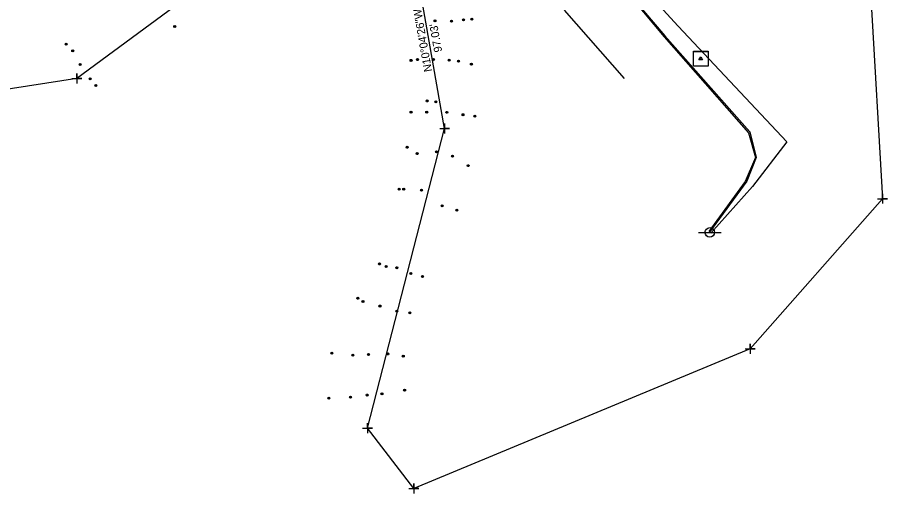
# Model space of a CAD drawing. Extents: x 1550153 to 1552579, y 809637 to 812160.
# Drawn here: x 1552025.7 to 1552462.6, y 809636.9 to 809876 of the extents above; entities that cross this region are included whole.
import ezdxf

# ---------------------------------------------------------------- set-up
doc = ezdxf.new("R2010")
doc.units = 0
for name, color, linetype in [('CTL Secondary Horizontal and Vertical CELL', 7, 'Continuous'), ('Default', 7, 'Continuous'), ('Exist Property Corner CELL', 7, 'Continuous'), ('Exist Property Line', 7, 'Continuous'), ('Exist Property Line Text', 7, 'Continuous'), ('Exist Right of Way Line', 7, 'Continuous'), ('Exist Survey Control Group', 7, 'Continuous'), ('Exist Utilities Telephone Pole CELL', 7, 'Continuous'), ('Exist Utilities Telephone UG Cable SUE LOS B', 7, 'Continuous'), ('Exist Utilities Telephone UG FO SUE LOS B', 7, 'Continuous')]:
    doc.layers.add(name, color=color, linetype=linetype)

# ---------------------------------------------------------------- blocks, each defined once
blk = doc.blocks.new('SurveyPointCell')
at = {"layer": 'Default'}
for p, q in [((-0.5, 0), (0.5, 0)), ((0, -0.5), (0, 0.5))]:
    blk.add_line(p, q, dxfattribs=at)
blk.add_circle((0, 0), 0.5, dxfattribs=at)

msp = doc.modelspace()

# ---------------------------------------------------------------- linework, layer by layer
at = {"layer": 'CTL Secondary Horizontal and Vertical CELL'}
for p, q in [((1552368.8, 809855.26), (1552368.8, 809855.26)), ((1552368.8, 809855.25), (1552368.8, 809855.25))]:
    msp.add_line(p, q, dxfattribs=at)
for points in [[(1552365.12, 809858.96), (1552372.53, 809858.96), (1552372.53, 809851.54), (1552365.12, 809851.54)], [(1552365.12, 809858.95), (1552372.53, 809858.95), (1552372.53, 809851.52), (1552365.12, 809851.52)]]:
    msp.add_lwpolyline(points, close=True, dxfattribs=at)
at = {"layer": 'Default'}
msp.add_line((1552368.8, 809855.26), (1552368.8, 809855.26), dxfattribs=at)
at = {"layer": 'Exist Property Corner CELL'}
for p, q in [((1552055.49, 809845.39), (1552055.49, 809845.39)), ((1552240.21, 809820.15), (1552240.21, 809820.15)), ((1552460.14, 809784.97), (1552460.14, 809784.97)), ((1552393.67, 809709.51), (1552393.67, 809709.51)), ((1552201.43, 809669.72), (1552201.43, 809669.72)), ((1552224.68, 809639.39), (1552224.68, 809639.39))]:
    msp.add_line(p, q, dxfattribs=at)
for points in [[(1552052.99, 809845.39), (1552057.99, 809845.39), (1552055.49, 809845.39), (1552055.49, 809847.89), (1552055.49, 809842.89)], [(1552237.71, 809820.15), (1552242.71, 809820.15), (1552240.21, 809820.15), (1552240.21, 809822.65), (1552240.21, 809817.65)], [(1552457.64, 809784.97), (1552462.64, 809784.97), (1552460.14, 809784.97), (1552460.14, 809787.47), (1552460.14, 809782.47)], [(1552391.17, 809709.51), (1552396.17, 809709.51), (1552393.67, 809709.51), (1552393.67, 809712.01), (1552393.67, 809707.01)], [(1552198.93, 809669.72), (1552203.93, 809669.72), (1552201.43, 809669.72), (1552201.43, 809672.22), (1552201.43, 809667.22)], [(1552222.18, 809639.39), (1552227.18, 809639.39), (1552224.68, 809639.39), (1552224.68, 809641.89), (1552224.68, 809636.89)]]:
    msp.add_lwpolyline(points, dxfattribs=at)
at = {"layer": 'Exist Property Line'}
for p, q in [((1552439.52, 810134.36), (1552460.15, 809784.96)), ((1552179.62, 809936.85), (1552055.49, 809845.39)), ((1552240.21, 809820.15), (1552223.24, 809915.69)), ((1552055.49, 809845.39), (1551998.3, 809836.53)), ((1552201.43, 809669.72), (1552240.21, 809820.15)), ((1552460.14, 809784.97), (1552393.67, 809709.51)), ((1552393.67, 809709.51), (1552224.68, 809639.39)), ((1552224.68, 809639.39), (1552201.43, 809669.72))]:
    msp.add_line(p, q, dxfattribs=at)
at = {"layer": 'Exist Right of Way Line'}
msp.add_line((1552300.27, 809879.66), (1552330.35, 809845.3), dxfattribs=at)
at = {"layer": 'Exist Survey Control Group'}
msp.add_line((1552368.8, 809855.25), (1552368.8, 809855.25), dxfattribs=at)
msp.add_lwpolyline([(1552367.93, 809854.75), (1552368.8, 809856.25), (1552369.66, 809854.75)], close=True, dxfattribs=at)
msp.add_circle((1552368.8, 809855.25), 0.5, dxfattribs=at)
at = {"layer": 'Exist Utilities Telephone Pole CELL'}
for p, q in [((1552367.68, 809768.01), (1552379.02, 809768.01)), ((1552373.35, 809768.01), (1552373.35, 809768.01))]:
    msp.add_line(p, q, dxfattribs=at)
msp.add_circle((1552373.35, 809768.01), 2.41, dxfattribs=at)
at = {"layer": 'Exist Utilities Telephone UG Cable SUE LOS B'}
msp.add_lwpolyline([(1552309.55, 809891.47), (1552312.19, 809891.91), (1552319.91, 809894.61), (1552329.89, 809900.42), (1552331.29, 809900.19), (1552357.54, 809871.63), (1552412.1, 809813.52), (1552394.77, 809791.06), (1552373.8, 809767.63)], dxfattribs=at)
at = {"layer": 'Exist Utilities Telephone UG FO SUE LOS B'}
for points in [[(1552252.06, 810038.28), (1552230.41, 810022.46), (1552228.43, 810020.33), (1552227.78, 810018.51), (1552285.44, 809948.57), (1552318.22, 809906.19), (1552325.57, 809896.61), (1552350.79, 809866.81), (1552393.46, 809818.55), (1552396.72, 809805.6), (1552391.99, 809793.83), (1552373.15, 809768.18)], [(1552311.27, 809890.39), (1552321.89, 809898.14), (1552325.31, 809896.34), (1552350.52, 809866.22), (1552392.74, 809818.07), (1552396.32, 809805.59), (1552391.17, 809793.53), (1552372.89, 809768.53)]]:
    msp.add_lwpolyline(points, dxfattribs=at)

# ---------------------------------------------------------------- block references
at = {"layer": 'Default'}
for p in [(1552235.36, 809874.27), (1552235.36, 809874.27), (1552243.71, 809874.15), (1552243.71, 809874.15), (1552249.72, 809874.81), (1552249.72, 809874.81), (1552253.92, 809875.09), (1552253.92, 809875.09), (1552104.63, 809871.47), (1552104.63, 809871.47), (1552050.16, 809862.5), (1552050.16, 809862.5), (1552053.42, 809859.19), (1552053.42, 809859.19), (1552057.19, 809852.35), (1552057.19, 809852.35), (1552223.32, 809854.42), (1552223.32, 809854.42), (1552226.58, 809854.79), (1552226.58, 809854.79), (1552234.56, 809854.89), (1552234.56, 809854.89), (1552242.53, 809854.49), (1552242.53, 809854.49), (1552247.13, 809854.03), (1552247.13, 809854.03), (1552253.62, 809852.46), (1552253.62, 809852.46), (1552062.13, 809845.12), (1552062.13, 809845.12), (1552065.02, 809841.84), (1552065.02, 809841.84), (1552231.42, 809834.03), (1552231.42, 809834.03), (1552235.79, 809833.66), (1552235.79, 809833.66), (1552223.31, 809828.47), (1552223.31, 809828.47), (1552231.19, 809828.39), (1552231.19, 809828.39), (1552241.31, 809828.33), (1552241.31, 809828.33), (1552249.42, 809827.15), (1552249.42, 809827.15), (1552255.35, 809826.36), (1552255.35, 809826.36), (1552221.42, 809810.77), (1552221.42, 809810.77), (1552226.36, 809807.59), (1552226.36, 809807.59), (1552236.16, 809808.44), (1552236.16, 809808.44), (1552244.19, 809806.36), (1552244.19, 809806.36), (1552251.99, 809801.55), (1552251.99, 809801.55), (1552217.38, 809789.8), (1552217.38, 809789.8), (1552219.63, 809789.78), (1552219.63, 809789.78), (1552228.59, 809789.28), (1552228.59, 809789.28), (1552238.96, 809781.42), (1552238.96, 809781.42), (1552246.36, 809779.15), (1552246.36, 809779.15), (1552207.45, 809752.19), (1552207.45, 809752.19), (1552210.85, 809750.96), (1552210.85, 809750.96), (1552216.17, 809750.33), (1552216.17, 809750.33), (1552223.24, 809747.38), (1552223.24, 809747.38), (1552229.03, 809745.95), (1552229.03, 809745.95), (1552196.6, 809734.94), (1552196.6, 809734.94), (1552199.2, 809733.3), (1552199.2, 809733.3), (1552207.73, 809731.07), (1552207.73, 809731.07), (1552216.25, 809728.47), (1552216.25, 809728.47), (1552222.74, 809727.7), (1552222.74, 809727.7), (1552183.55, 809707.38), (1552183.55, 809707.38), (1552194.11, 809706.44), (1552194.11, 809706.44), (1552201.92, 809706.73), (1552201.92, 809706.73), (1552211.67, 809707), (1552211.67, 809707), (1552219.44, 809705.87), (1552219.44, 809705.87), (1552201.24, 809686.39), (1552201.24, 809686.39), (1552208.73, 809687.03), (1552208.73, 809687.03), (1552220.11, 809688.81), (1552220.11, 809688.81), (1552182.02, 809684.75), (1552182.02, 809684.75), (1552192.97, 809685.3), (1552192.97, 809685.3)]:
    msp.add_blockref('SurveyPointCell', p, dxfattribs=at)

# ---------------------------------------------------------------- texts
at = {"layer": 'Exist Property Line Text'}
for s, p in [('N10°04\'26"W', (1552233.93, 809849.02)), ("97.03'", (1552238.98, 809858.86))]:
    msp.add_text(s, height=4.02, rotation=100.0739, dxfattribs=at).set_placement(p)

doc.saveas('drawing.dxf')
